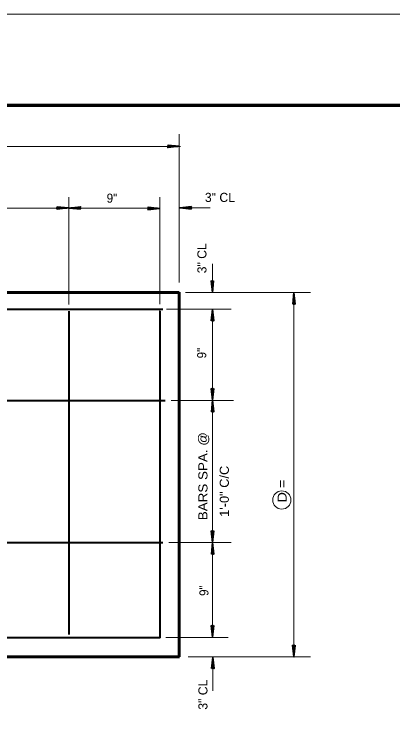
# Model space of a CAD drawing. Extents: x 4.49 to 7.69, y 0.28 to 2.27.
# Drawn here: x 5.396 to 5.742, y 1.617 to 2.269 of the extents above; entities that cross this region are included whole.
import ezdxf
from ezdxf.enums import TextEntityAlignment as Align

# ---------------------------------------------------------------- set-up
doc = ezdxf.new("R2010")
doc.units = 0
doc.header["$LTSCALE"] = 0.0033
doc.layers.add('1', color=7, linetype='Continuous', lineweight=35)

msp = doc.modelspace()

# ---------------------------------------------------------------- linework, layer by layer
at = {"layer": '1', "lineweight": 13}
for p, q in [((4.492417, 2.2695), (7.688833, 2.2695)), ((5.546917, 2.159833), (5.546917, 2.024083)), ((4.79675, 2.148667), (5.547917, 2.148667)), ((5.445667, 2.004), (5.445667, 2.102167)), ((5.529, 2.00425), (5.529, 2.102167)), ((4.814167, 2.092), (5.525, 2.092)), ((5.557417, 2.092417), (5.57525, 2.092417)), ((5.577167, 2.024833), (5.577167, 2.041167)), ((5.552583, 2.015), (5.666917, 2.015)), ((5.651833, 2.013417), (5.651833, 1.681583)), ((5.529, 1.998), (5.529, 1.99875)), ((5.535167, 1.99975), (5.594417, 1.99975)), ((5.577333, 1.998583), (5.577333, 1.706917)), ((5.539583, 1.916333), (5.596417, 1.916333)), ((5.537417, 1.78625), (5.594417, 1.78625)), ((5.534583, 1.699583), (5.59175, 1.699583)), ((5.666917, 1.681667), (5.554917, 1.681667)), ((5.577583, 1.65075), (5.577583, 1.671583))]:
    msp.add_line(p, q, dxfattribs=at)
at = {"layer": '1'}
for p, q in [((5.536333, 2.14875), (5.546917, 2.14875)), ((5.5365, 2.148083), (5.543833, 2.148833)), ((5.536583, 2.14975), (5.544417, 2.148833)), ((5.536583, 2.14975), (5.544417, 2.148833)), ((5.536583, 2.149667), (5.544417, 2.148833)), ((5.536583, 2.149583), (5.544417, 2.14875)), ((5.536583, 2.149583), (5.544417, 2.148583)), ((5.536583, 2.147917), (5.543917, 2.14875)), ((5.536583, 2.147833), (5.543917, 2.148583)), ((5.536583, 2.147667), (5.543917, 2.1485)), ((5.434833, 2.092417), (5.445417, 2.092417)), ((5.435, 2.09175), (5.442333, 2.0925)), ((5.435083, 2.093417), (5.442917, 2.0925)), ((5.435083, 2.093417), (5.442917, 2.0925)), ((5.435083, 2.093333), (5.442917, 2.0925)), ((5.435083, 2.09325), (5.442917, 2.092417)), ((5.435083, 2.09325), (5.442917, 2.09225)), ((5.435083, 2.091583), (5.442417, 2.092417)), ((5.435083, 2.0915), (5.442417, 2.09225)), ((5.435083, 2.091333), (5.442417, 2.092167)), ((5.456583, 2.09225), (5.446, 2.09225)), ((5.456333, 2.091417), (5.4485, 2.092417)), ((5.456333, 2.091417), (5.4485, 2.09225)), ((5.456333, 2.09125), (5.4485, 2.092167)), ((5.456333, 2.09125), (5.4485, 2.092167)), ((5.456333, 2.091333), (5.4485, 2.092167)), ((5.456333, 2.093333), (5.449, 2.0925)), ((5.456333, 2.093167), (5.449, 2.092417)), ((5.456333, 2.093083), (5.449, 2.09225)), ((5.456417, 2.092917), (5.449083, 2.092167)), ((5.518167, 2.091917), (5.52875, 2.091917)), ((5.518333, 2.09125), (5.525667, 2.092)), ((5.518417, 2.092917), (5.52625, 2.092)), ((5.518417, 2.092917), (5.52625, 2.092)), ((5.518417, 2.092833), (5.52625, 2.092)), ((5.518417, 2.09275), (5.52625, 2.091917)), ((5.518417, 2.09275), (5.52625, 2.09175)), ((5.518417, 2.091083), (5.52575, 2.091917)), ((5.518417, 2.091), (5.52575, 2.09175)), ((5.518417, 2.090833), (5.52575, 2.091667)), ((5.557917, 2.092417), (5.547333, 2.092417)), ((5.557667, 2.091583), (5.549833, 2.092583)), ((5.557667, 2.091583), (5.549833, 2.092417)), ((5.557667, 2.091417), (5.549833, 2.092333)), ((5.557667, 2.091417), (5.549833, 2.092333)), ((5.557667, 2.0915), (5.549833, 2.092333)), ((5.557667, 2.0935), (5.550333, 2.092667)), ((5.557667, 2.093333), (5.550333, 2.092583)), ((5.557667, 2.09325), (5.550333, 2.092417)), ((5.55775, 2.093083), (5.550417, 2.092333)), ((5.576083, 2.025417), (5.576917, 2.018083)), ((5.57625, 2.025417), (5.577, 2.018083)), ((5.576333, 2.025417), (5.577167, 2.018083)), ((5.5765, 2.0255), (5.57725, 2.018167)), ((5.578, 2.025417), (5.577, 2.017583)), ((5.577167, 2.025667), (5.577167, 2.015083)), ((5.578, 2.025417), (5.577167, 2.017583)), ((5.578167, 2.025417), (5.57725, 2.017583)), ((5.578167, 2.025417), (5.57725, 2.017583)), ((5.578083, 2.025417), (5.57725, 2.017583)), ((5.650833, 2.004667), (5.65175, 2.0125)), ((5.650833, 2.004667), (5.65175, 2.0125)), ((5.650917, 2.004667), (5.65175, 2.0125)), ((5.651, 2.004667), (5.651833, 2.0125)), ((5.651, 2.004667), (5.652, 2.0125)), ((5.6525, 2.004583), (5.65175, 2.011917)), ((5.651833, 2.004417), (5.651833, 2.015)), ((5.652667, 2.004667), (5.651833, 2.012)), ((5.65275, 2.004667), (5.652, 2.012)), ((5.652917, 2.004667), (5.652083, 2.012)), ((5.57625, 1.989333), (5.577167, 1.997167)), ((5.57625, 1.989333), (5.577167, 1.997167)), ((5.576333, 1.989333), (5.577167, 1.997167)), ((5.576417, 1.989333), (5.57725, 1.997167)), ((5.576417, 1.989333), (5.577417, 1.997167)), ((5.57725, 1.989083), (5.57725, 1.999667)), ((5.577917, 1.98925), (5.577167, 1.996583)), ((5.578083, 1.989333), (5.57725, 1.996667)), ((5.578167, 1.989333), (5.577417, 1.996667)), ((5.578333, 1.989333), (5.5775, 1.996667)), ((5.57625, 1.926833), (5.577083, 1.9195)), ((5.576417, 1.926833), (5.577167, 1.9195)), ((5.5765, 1.926833), (5.577333, 1.9195)), ((5.576667, 1.926917), (5.577417, 1.919583)), ((5.578167, 1.926833), (5.577167, 1.919)), ((5.577333, 1.927083), (5.577333, 1.9165)), ((5.578167, 1.926833), (5.577333, 1.919)), ((5.578333, 1.926833), (5.577417, 1.919)), ((5.578333, 1.926833), (5.577417, 1.919)), ((5.57825, 1.926833), (5.577417, 1.919)), ((5.576333, 1.906083), (5.57725, 1.913917)), ((5.576333, 1.906083), (5.57725, 1.913917)), ((5.576417, 1.906083), (5.57725, 1.913917)), ((5.5765, 1.906083), (5.577333, 1.913917)), ((5.5765, 1.906083), (5.5775, 1.913917)), ((5.578, 1.906), (5.57725, 1.913333)), ((5.577333, 1.905833), (5.577333, 1.916417)), ((5.578167, 1.906083), (5.577333, 1.913417)), ((5.57825, 1.906083), (5.5775, 1.913417)), ((5.578417, 1.906083), (5.577583, 1.913417)), ((5.57625, 1.79675), (5.577083, 1.789417)), ((5.576417, 1.79675), (5.577167, 1.789417)), ((5.5765, 1.79675), (5.577333, 1.789417)), ((5.576667, 1.796833), (5.577417, 1.7895)), ((5.578167, 1.79675), (5.577167, 1.788917)), ((5.577333, 1.797), (5.577333, 1.786417)), ((5.578167, 1.79675), (5.577333, 1.788917)), ((5.578333, 1.79675), (5.577417, 1.788917)), ((5.578333, 1.79675), (5.577417, 1.788917)), ((5.57825, 1.79675), (5.577417, 1.788917)), ((5.576333, 1.775917), (5.57725, 1.78375)), ((5.576333, 1.775917), (5.57725, 1.78375)), ((5.576417, 1.775917), (5.57725, 1.78375)), ((5.5765, 1.775917), (5.577333, 1.78375)), ((5.5765, 1.775917), (5.5775, 1.78375)), ((5.578, 1.775833), (5.57725, 1.783167)), ((5.577333, 1.775667), (5.577333, 1.78625)), ((5.578167, 1.775917), (5.577333, 1.78325)), ((5.57825, 1.775917), (5.5775, 1.78325)), ((5.578417, 1.775917), (5.577583, 1.78325)), ((5.57625, 1.710083), (5.577083, 1.70275)), ((5.576417, 1.710083), (5.577167, 1.70275)), ((5.5765, 1.710083), (5.577333, 1.70275)), ((5.576667, 1.710167), (5.577417, 1.702833)), ((5.578167, 1.710083), (5.577167, 1.70225)), ((5.577333, 1.710333), (5.577333, 1.69975)), ((5.578167, 1.710083), (5.577333, 1.70225)), ((5.578333, 1.710083), (5.577417, 1.70225)), ((5.578333, 1.710083), (5.577417, 1.70225)), ((5.57825, 1.710083), (5.577417, 1.70225)), ((5.65075, 1.692083), (5.651583, 1.68475)), ((5.650917, 1.692083), (5.651667, 1.68475)), ((5.651, 1.692083), (5.651833, 1.68475)), ((5.651167, 1.692167), (5.651917, 1.684833)), ((5.652667, 1.692083), (5.651667, 1.68425)), ((5.651833, 1.692333), (5.651833, 1.68175)), ((5.652667, 1.692083), (5.651833, 1.68425)), ((5.652833, 1.692083), (5.651917, 1.68425)), ((5.652833, 1.692083), (5.651917, 1.68425)), ((5.65275, 1.692083), (5.651917, 1.68425)), ((5.576583, 1.67125), (5.5775, 1.679083)), ((5.576583, 1.67125), (5.5775, 1.679083)), ((5.576667, 1.67125), (5.5775, 1.679083)), ((5.57675, 1.67125), (5.577583, 1.679083)), ((5.57675, 1.67125), (5.57775, 1.679083)), ((5.57825, 1.671167), (5.5775, 1.6785)), ((5.577583, 1.671), (5.577583, 1.681583)), ((5.578417, 1.67125), (5.577583, 1.678583)), ((5.5785, 1.67125), (5.57775, 1.678583)), ((5.578667, 1.67125), (5.577833, 1.678583))]:
    msp.add_line(p, q, dxfattribs=at)
at = {"layer": '1', "lineweight": 60}
for p, q in [((5.546917, 2.015167), (5.546917, 1.681667)), ((5.547, 1.681667), (4.796917, 1.681667))]:
    msp.add_line(p, q, dxfattribs=at)
at = {"layer": '1', "lineweight": 40}
for p, q in [((5.445667, 1.998), (5.445667, 1.702333)), ((5.529, 1.998), (5.529, 1.699083))]:
    msp.add_line(p, q, dxfattribs=at)
at = {"layer": '1', "lineweight": 70}
msp.add_lwpolyline([(7.605833, 0.366083), (7.605833, 2.186167), (4.659167, 2.186167), (4.659167, 0.366083)], dxfattribs=at)
at = {"layer": '1'}
for points in [[(5.536333, 2.149833), (5.546917, 2.14875), (5.536333, 2.147583), (5.536917, 2.14875)], [(5.537083, 2.148833), (5.54175, 2.148917), (5.54175, 2.148833), (5.540833, 2.148833), (5.537083, 2.148917), (5.540083, 2.149), (5.536917, 2.149083), (5.539167, 2.149167), (5.536917, 2.14925), (5.540417, 2.149), (5.545083, 2.148833), (5.544167, 2.148583), (5.545417, 2.148583), (5.537083, 2.148583), (5.5395, 2.148417), (5.536917, 2.148417), (5.54225, 2.148833), (5.536917, 2.148167)], [(5.434833, 2.0935), (5.445417, 2.092417), (5.434833, 2.09125), (5.435417, 2.092417)], [(5.435583, 2.0925), (5.44025, 2.092583), (5.44025, 2.0925), (5.439333, 2.0925), (5.435583, 2.092583), (5.438583, 2.092667), (5.435417, 2.09275), (5.437667, 2.092833), (5.435417, 2.092917), (5.438917, 2.092667), (5.443583, 2.0925), (5.442667, 2.09225), (5.443917, 2.09225), (5.435583, 2.09225), (5.438, 2.092083), (5.435417, 2.092083), (5.44075, 2.0925), (5.435417, 2.091833)], [(5.456583, 2.091167), (5.446, 2.09225), (5.456583, 2.093417), (5.456, 2.09225)], [(5.455833, 2.092167), (5.451167, 2.092083), (5.451167, 2.092167), (5.452083, 2.092167), (5.455833, 2.092083), (5.452833, 2.092), (5.456, 2.091917), (5.45375, 2.091833), (5.456, 2.09175), (5.4525, 2.092), (5.447833, 2.092167), (5.44875, 2.092417), (5.4475, 2.092417), (5.455833, 2.092417), (5.453417, 2.092583), (5.456, 2.092583), (5.450667, 2.092167), (5.456, 2.092833)], [(5.518167, 2.093), (5.52875, 2.091917), (5.518167, 2.09075), (5.51875, 2.091917)], [(5.518917, 2.092), (5.523583, 2.092083), (5.523583, 2.092), (5.522667, 2.092), (5.518917, 2.092083), (5.521917, 2.092167), (5.51875, 2.09225), (5.521, 2.092333), (5.51875, 2.092417), (5.52225, 2.092167), (5.526917, 2.092), (5.526, 2.09175), (5.52725, 2.09175), (5.518917, 2.09175), (5.521333, 2.091583), (5.51875, 2.091583), (5.524083, 2.092), (5.51875, 2.091333)], [(5.557917, 2.091333), (5.547333, 2.092417), (5.557917, 2.093583), (5.557333, 2.092417)], [(5.557167, 2.092333), (5.5525, 2.09225), (5.5525, 2.092333), (5.553417, 2.092333), (5.557167, 2.09225), (5.554167, 2.092167), (5.557333, 2.092083), (5.555083, 2.092), (5.557333, 2.091917), (5.553833, 2.092167), (5.549167, 2.092333), (5.550083, 2.092583), (5.548833, 2.092583), (5.557167, 2.092583), (5.55475, 2.09275), (5.557333, 2.09275), (5.552, 2.092333), (5.557333, 2.093)], [(5.57825, 2.025667), (5.577167, 2.015083), (5.576, 2.025667), (5.577167, 2.025083)], [(5.57725, 2.024917), (5.577333, 2.02025), (5.57725, 2.02025), (5.57725, 2.021167), (5.577333, 2.024917), (5.577417, 2.021917), (5.5775, 2.025083), (5.577583, 2.022833), (5.577667, 2.025083), (5.577417, 2.021583), (5.57725, 2.016917), (5.577, 2.017833), (5.577, 2.016583), (5.577, 2.024917), (5.576833, 2.0225), (5.576833, 2.025083), (5.57725, 2.01975), (5.576583, 2.025083)], [(5.65075, 2.004417), (5.651833, 2.015), (5.653, 2.004417), (5.651833, 2.005)], [(5.65175, 2.005167), (5.651667, 2.009833), (5.65175, 2.009833), (5.65175, 2.008917), (5.651667, 2.005167), (5.651583, 2.008167), (5.6515, 2.005), (5.651417, 2.00725), (5.651333, 2.005), (5.651583, 2.0085), (5.65175, 2.013167), (5.652, 2.01225), (5.652, 2.0135), (5.652, 2.005167), (5.652167, 2.007583), (5.652167, 2.005), (5.65175, 2.010333), (5.652417, 2.005)], [(5.576167, 1.989083), (5.57725, 1.999667), (5.578417, 1.989083), (5.57725, 1.989667)], [(5.577167, 1.989833), (5.577083, 1.9945), (5.577167, 1.9945), (5.577167, 1.993583), (5.577083, 1.989833), (5.577, 1.992833), (5.576917, 1.989667), (5.576833, 1.991917), (5.57675, 1.989667), (5.577, 1.993167), (5.577167, 1.997833), (5.577417, 1.996917), (5.577417, 1.998167), (5.577417, 1.989833), (5.577583, 1.99225), (5.577583, 1.989667), (5.577167, 1.995), (5.577833, 1.989667)], [(5.578417, 1.927083), (5.577333, 1.9165), (5.576167, 1.927083), (5.577333, 1.9265)], [(5.577417, 1.926333), (5.5775, 1.921667), (5.577417, 1.921667), (5.577417, 1.922583), (5.5775, 1.926333), (5.577583, 1.923333), (5.577667, 1.9265), (5.57775, 1.92425), (5.577833, 1.9265), (5.577583, 1.923), (5.577417, 1.918333), (5.577167, 1.91925), (5.577167, 1.918), (5.577167, 1.926333), (5.577, 1.923917), (5.577, 1.9265), (5.577417, 1.921167), (5.57675, 1.9265)], [(5.57625, 1.905833), (5.577333, 1.916417), (5.5785, 1.905833), (5.577333, 1.906417)], [(5.57725, 1.906583), (5.577167, 1.91125), (5.57725, 1.91125), (5.57725, 1.910333), (5.577167, 1.906583), (5.577083, 1.909583), (5.577, 1.906417), (5.576917, 1.908667), (5.576833, 1.906417), (5.577083, 1.909917), (5.57725, 1.914583), (5.5775, 1.913667), (5.5775, 1.914917), (5.5775, 1.906583), (5.577667, 1.909), (5.577667, 1.906417), (5.57725, 1.91175), (5.577917, 1.906417)], [(5.578417, 1.797), (5.577333, 1.786417), (5.576167, 1.797), (5.577333, 1.796417)], [(5.577417, 1.79625), (5.5775, 1.791583), (5.577417, 1.791583), (5.577417, 1.7925), (5.5775, 1.79625), (5.577583, 1.79325), (5.577667, 1.796417), (5.57775, 1.794167), (5.577833, 1.796417), (5.577583, 1.792917), (5.577417, 1.78825), (5.577167, 1.789167), (5.577167, 1.787917), (5.577167, 1.79625), (5.577, 1.793833), (5.577, 1.796417), (5.577417, 1.791083), (5.57675, 1.796417)], [(5.57625, 1.775667), (5.577333, 1.78625), (5.5785, 1.775667), (5.577333, 1.77625)], [(5.57725, 1.776417), (5.577167, 1.781083), (5.57725, 1.781083), (5.57725, 1.780167), (5.577167, 1.776417), (5.577083, 1.779417), (5.577, 1.77625), (5.576917, 1.7785), (5.576833, 1.77625), (5.577083, 1.77975), (5.57725, 1.784417), (5.5775, 1.7835), (5.5775, 1.78475), (5.5775, 1.776417), (5.577667, 1.778833), (5.577667, 1.77625), (5.57725, 1.781583), (5.577917, 1.77625)], [(5.578417, 1.710333), (5.577333, 1.69975), (5.576167, 1.710333), (5.577333, 1.70975)], [(5.577417, 1.709583), (5.5775, 1.704917), (5.577417, 1.704917), (5.577417, 1.705833), (5.5775, 1.709583), (5.577583, 1.706583), (5.577667, 1.70975), (5.57775, 1.7075), (5.577833, 1.70975), (5.577583, 1.70625), (5.577417, 1.701583), (5.577167, 1.7025), (5.577167, 1.70125), (5.577167, 1.709583), (5.577, 1.707167), (5.577, 1.70975), (5.577417, 1.704417), (5.57675, 1.70975)], [(5.652917, 1.692333), (5.651833, 1.68175), (5.650667, 1.692333), (5.651833, 1.69175)], [(5.651917, 1.691583), (5.652, 1.686917), (5.651917, 1.686917), (5.651917, 1.687833), (5.652, 1.691583), (5.652083, 1.688583), (5.652167, 1.69175), (5.65225, 1.6895), (5.652333, 1.69175), (5.652083, 1.68825), (5.651917, 1.683583), (5.651667, 1.6845), (5.651667, 1.68325), (5.651667, 1.691583), (5.6515, 1.689167), (5.6515, 1.69175), (5.651917, 1.686417), (5.65125, 1.69175)], [(5.5765, 1.671), (5.577583, 1.681583), (5.57875, 1.671), (5.577583, 1.671583)], [(5.5775, 1.67175), (5.577417, 1.676417), (5.5775, 1.676417), (5.5775, 1.6755), (5.577417, 1.67175), (5.577333, 1.67475), (5.57725, 1.671583), (5.577167, 1.673833), (5.577083, 1.671583), (5.577333, 1.675083), (5.5775, 1.67975), (5.57775, 1.678833), (5.57775, 1.680083), (5.57775, 1.67175), (5.577917, 1.674167), (5.577917, 1.671583), (5.5775, 1.676917), (5.578167, 1.671583)]]:
    msp.add_lwpolyline(points, close=True, dxfattribs=at)
for points in [[(5.537083, 2.148833), (5.536667, 2.149583), (5.536917, 2.149333), (5.537083, 2.149), (5.537333, 2.149083), (5.537167, 2.149417), (5.537, 2.148667), (5.536833, 2.148167), (5.536583, 2.14775)], [(5.435583, 2.0925), (5.435167, 2.09325), (5.435417, 2.093), (5.435583, 2.092667), (5.435833, 2.09275), (5.435667, 2.093083), (5.4355, 2.092333), (5.435333, 2.091833), (5.435083, 2.091417)], [(5.455833, 2.092167), (5.45625, 2.091417), (5.456, 2.091667), (5.455833, 2.092), (5.455583, 2.091917), (5.45575, 2.091583), (5.455917, 2.092333), (5.456083, 2.092833), (5.456333, 2.09325)], [(5.518917, 2.092), (5.5185, 2.09275), (5.51875, 2.0925), (5.518917, 2.092167), (5.519167, 2.09225), (5.519, 2.092583), (5.518833, 2.091833), (5.518667, 2.091333), (5.518417, 2.090917)], [(5.557167, 2.092333), (5.557583, 2.091583), (5.557333, 2.091833), (5.557167, 2.092167), (5.556917, 2.092083), (5.557083, 2.09175), (5.55725, 2.0925), (5.557417, 2.093), (5.557667, 2.093417)], [(5.57725, 2.024917), (5.578, 2.025333), (5.57775, 2.025083), (5.577417, 2.024917), (5.5775, 2.024667), (5.577833, 2.024833), (5.577083, 2.025), (5.576583, 2.025167), (5.576167, 2.025417)], [(5.65175, 2.005167), (5.651, 2.00475), (5.65125, 2.005), (5.651583, 2.005167), (5.6515, 2.005417), (5.651167, 2.00525), (5.651917, 2.005083), (5.652417, 2.004917), (5.652833, 2.004667)], [(5.577167, 1.989833), (5.576417, 1.989417), (5.576667, 1.989667), (5.577, 1.989833), (5.576917, 1.990083), (5.576583, 1.989917), (5.577333, 1.98975), (5.577833, 1.989583), (5.57825, 1.989333)], [(5.577417, 1.926333), (5.578167, 1.92675), (5.577917, 1.9265), (5.577583, 1.926333), (5.577667, 1.926083), (5.578, 1.92625), (5.57725, 1.926417), (5.57675, 1.926583), (5.576333, 1.926833)], [(5.57725, 1.906583), (5.5765, 1.906167), (5.57675, 1.906417), (5.577083, 1.906583), (5.577, 1.906833), (5.576667, 1.906667), (5.577417, 1.9065), (5.577917, 1.906333), (5.578333, 1.906083)], [(5.577417, 1.79625), (5.578167, 1.796667), (5.577917, 1.796417), (5.577583, 1.79625), (5.577667, 1.796), (5.578, 1.796167), (5.57725, 1.796333), (5.57675, 1.7965), (5.576333, 1.79675)], [(5.57725, 1.776417), (5.5765, 1.776), (5.57675, 1.77625), (5.577083, 1.776417), (5.577, 1.776667), (5.576667, 1.7765), (5.577417, 1.776333), (5.577917, 1.776167), (5.578333, 1.775917)], [(5.577417, 1.709583), (5.578167, 1.71), (5.577917, 1.70975), (5.577583, 1.709583), (5.577667, 1.709333), (5.578, 1.7095), (5.57725, 1.709667), (5.57675, 1.709833), (5.576333, 1.710083)], [(5.651917, 1.691583), (5.652667, 1.692), (5.652417, 1.69175), (5.652083, 1.691583), (5.652167, 1.691333), (5.6525, 1.6915), (5.65175, 1.691667), (5.65125, 1.691833), (5.650833, 1.692083)], [(5.5775, 1.67175), (5.57675, 1.671333), (5.577, 1.671583), (5.577333, 1.67175), (5.57725, 1.672), (5.576917, 1.671833), (5.577667, 1.671667), (5.578167, 1.6715), (5.578583, 1.67125)]]:
    msp.add_lwpolyline(points, dxfattribs=at)
at = {"layer": '1', "lineweight": 60}
msp.add_lwpolyline([(4.796917, 2.015), (5.014, 2.015), (5.54675, 2.015)], dxfattribs=at)
at = {"layer": '1', "lineweight": 40}
for points in [[(5.104417, 2.003917), (5.18775, 2.003917), (5.195, 1.99975), (5.531917, 1.99975)], [(5.106417, 1.9205), (5.18975, 1.9205), (5.197, 1.916333), (5.533917, 1.916333)], [(5.104417, 1.790417), (5.18775, 1.790417), (5.195, 1.78625), (5.531917, 1.78625)], [(5.10175, 1.70375), (5.185083, 1.70375), (5.192333, 1.699583), (5.52925, 1.699583)]]:
    msp.add_lwpolyline(points, dxfattribs=at)
at = {"layer": '1', "lineweight": 13}
msp.add_circle((5.64075, 1.825167), 0.008333, dxfattribs=at)

# ---------------------------------------------------------------- texts
at = {"layer": '1', "width": 0.95}
msp.add_text('9"', height=0.008334, dxfattribs=at).set_placement((5.48525, 2.097167), align=Align.CENTER)
at = {"layer": '1'}
msp.add_text('3" CL', height=0.008334, dxfattribs=at).set_placement((5.570333, 2.097833))
for p in [(5.57175, 2.032583), (5.572667, 1.633417)]:
    msp.add_text('3" CL', height=0.008334, rotation=90, dxfattribs=at).set_placement(p)
at = {"layer": '1', "width": 0.95}
for p in [(5.571583, 1.959583), (5.573583, 1.742333)]:
    msp.add_text('9"', height=0.008334, rotation=90, dxfattribs=at).set_placement(p, align=Align.CENTER)
at = {"layer": '1'}
for s, width, p in [('BARS SPA. @', 1.1, (5.572667, 1.80675)), ('1\'-0" C/C', 1.05, (5.59225, 1.809833)), ('D =      ', 1.2, (5.645167, 1.822833))]:
    msp.add_text(s, height=0.008334, rotation=90, dxfattribs=dict(at, width=width)).set_placement(p)

doc.saveas('drawing.dxf')
